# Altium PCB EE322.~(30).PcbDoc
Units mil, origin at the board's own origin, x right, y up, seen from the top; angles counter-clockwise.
Board outline 3640 x 2960 mil, 2 copper layers (Top Layer, Bottom Layer); 48 components, 23 nets, 113 pads, 0 vias.
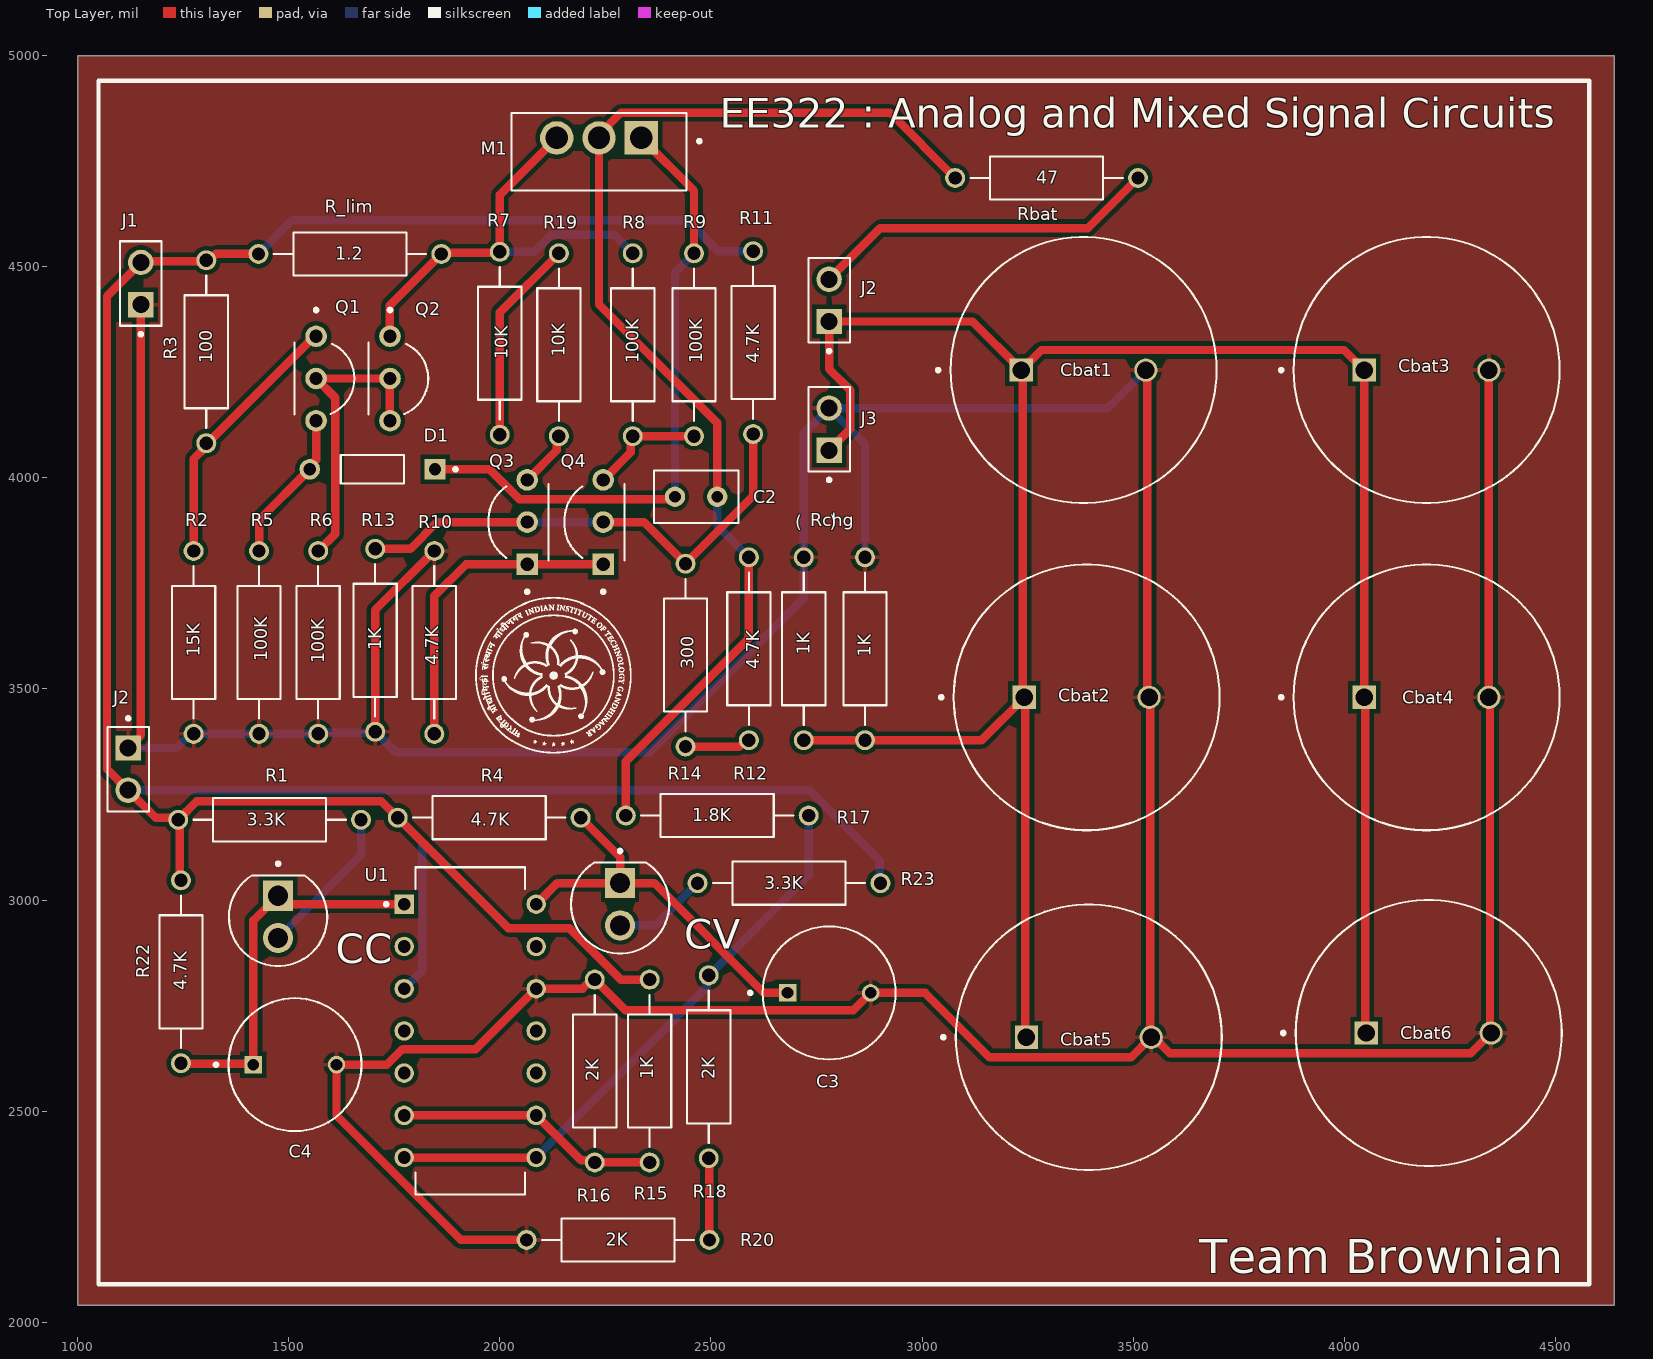
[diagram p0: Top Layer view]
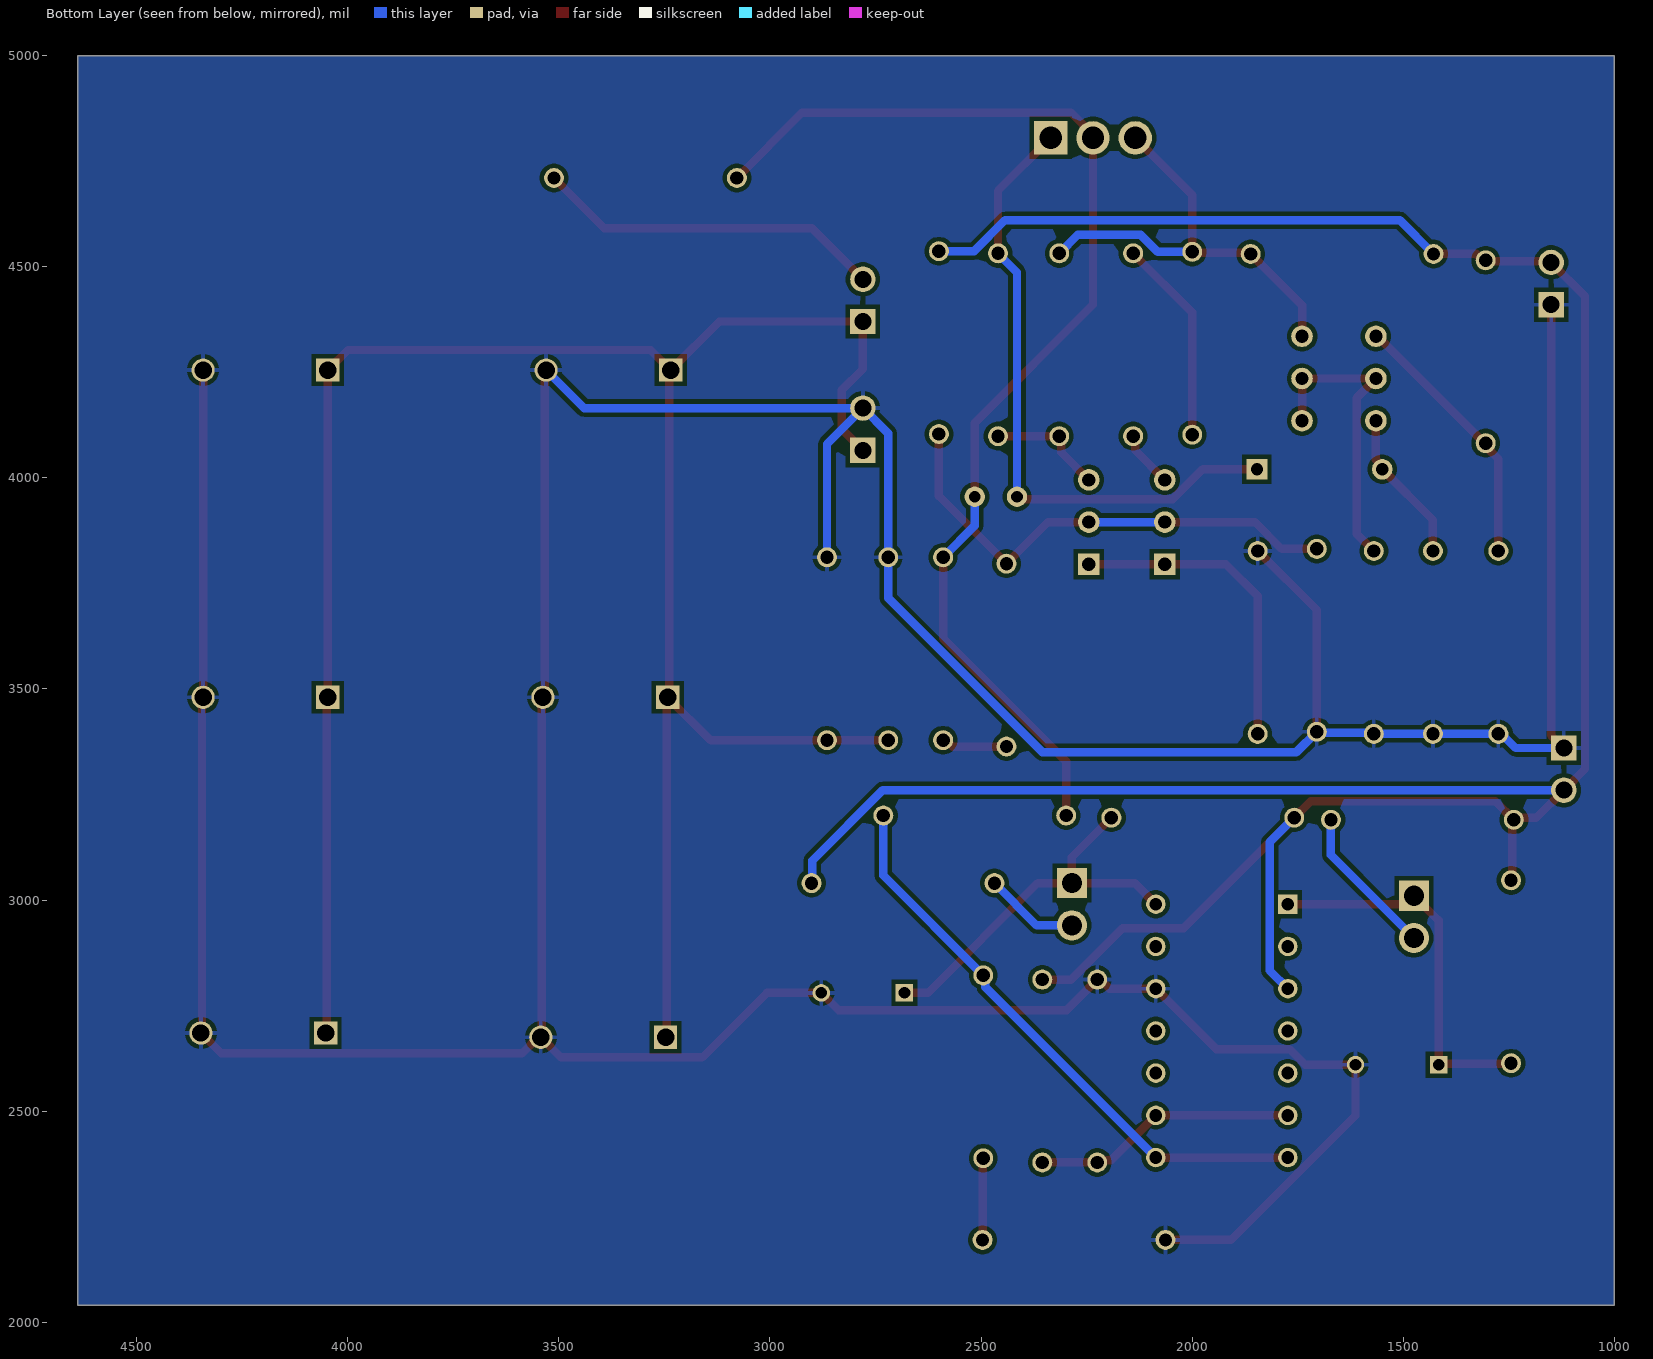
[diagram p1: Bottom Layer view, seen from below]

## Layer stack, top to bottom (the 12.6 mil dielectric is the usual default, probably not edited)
Top Solder: solder mask 0.4, Solder Resist, Dk 3.5
Top Layer: signal copper 1.4
Dielectric 1: dielectric 12.6, FR-4, Dk 4.8
Bottom Layer: signal copper 1.4
Bottom Solder: solder mask 0.4, Solder Resist, Dk 3.5

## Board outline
4640,5000 4640,2040 1000,2040 1000,5000

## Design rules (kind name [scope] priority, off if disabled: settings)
Clearance [All] p1: gap=10 ignorepadtopadclearanceinfootprint=FALSE
Height [All] p1: minheight=0 maxheight=1500 prefheight=500
PolygonConnect [All] p1: connectstyle=Relief reliefconductorwidth=10 reliefentries=4 polygonreliefangle="90 Angle" airgapwidth=10
RoutingVias [All] p1: holewidth=28 width=50 viastyle="Through Hole" minholewidth=28 minwidth=50 maxholewidth=28 maxwidth=50
SilkToSolderMaskClearance [IsPad] p1: minsilkscreentomaskgap=9 clearancetoexposedcopper=TRUE
SolderMaskExpansion [All] p1: expansion=0 istentingtop=FALSE
Width [All] p1: maxlimit=40 minlimit=20 preferedwidth=20
28 further rules are at their usual default settings.

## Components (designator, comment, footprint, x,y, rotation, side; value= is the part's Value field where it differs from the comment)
C2 "" CAPRR254W50L508T317H508 2465,3955 r0 top
C3 "ECEA1HKA330Q" CAPPRD500W45D800H700 2780,2780 r0 top
C4 "ECEA1HKA330Q" CAPPRD500W45D800H700 1515,2610 r0 top
Cbat1 "" CAPPRD750W80D1600H3150 3382.64,4255 r0 top
Cbat2 "" CAPPRD750W80D1600H3150 3390,3480 r0 top
Cbat3 "" CAPPRD750W80D1600H3150 4195,4255 r0 top
Cbat4 "" CAPPRD750W80D1600H3150 4195,3480 r0 top
Cbat5 "" CAPPRD750W80D1600H3150 3395,2675 r0 top
Cbat6 "" CAPPRD750W80D1600H3150 4200,2685 r0 top
CC "" LEDRD254W57D500H1070 1475,2960 r270 top
CV "" LEDRD254W57D500H1070 2285,2990 r270 top
D1 "1N4148" DIOAD753W49L380D172B 1698.37,4020 r180 top
J1 "" CONNFLY_DS1021-1X2SF11-B 1150,4460 r90 top
J2 "" CONNFLY_DS1021-1X2SF11-B 1120,3310 r270 top
J2 "" CONNFLY_DS1021-1X2SF11-B 2780,4420 r90 top
J3 "" CONNFLY_DS1021-1X2SF11-B 2780,4115 r90 top
M1 "" TO254P1052X465X1989-3 2335,4805 r180 top
Q1 "" TO92254P460H750-3#1 1565,4235 r270 top
Q2 "" TO92254P460H750-3#1 1740,4235 r270 top
Q3 "" TO92254P460H750-3#2 2065,3895 r90 top
Q4 "" TO92254P460H750-3#2 2245,3895 r90 top
R1 "" RESAD1100W55L680D260 1455,3190 r180 top
R2 "" RESAD1100W55L680D260 1275,3610 r90 top
R3 "" RESAD1100W55L680D260 1305,4298.46 r90 top
R4 "" RESAD1100W55L680D260 1975,3195 r180 top
R5 "" RESAD1100W55L680D260 1430,3610 r90 top
R6 "" RESAD1100W55L680D260 1570,3610 r90 top
R7 "" RESAD1100W55L680D260 2000,4318.46 r90 top
R8 "" RESAD1100W55L680D260 2315,4315 r90 top
R9 "" RESAD1100W55L680D260 2460,4315 r90 top
R10 "" RESAD1100W55L680D260 1845,3610 r270 top
R11 "" RESAD1100W55L680D260 2600,4320 r90 top
R12 "" RESAD1100W55L680D260 2590,3595 r90 top
R13 "" RESAD1100W55L680D260 1705,3615 r90 top
R14 "" RESAD1100W55L680D260 2440,3580 r270 top
R15 "MFR-25FBF52-10K" RESAD1100W55L680D260 2355,2595 r90 top
R16 "MFR-25FBF52-10K" RESAD1100W55L680D260 2225,2595 r270 top
R17 "MFR-25FBF52-10K" RESAD1100W55L680D260 2515,3200 r180 top
R18 "MFR-25FBF52-10K" RESAD1100W55L680D260 2495,2605 r90 top
R19 "" RESAD1100W55L680D260 2140,4315 r90 top
R20 "MFR-25FBF52-10K" RESAD1100W55L680D260 2280,2195 r0 top
R22 "" RESAD1100W55L680D260 1245,2830 r90 top
R23 "" RESAD1100W55L680D260 2685,3040 r0 top
R_lim "" RESAD1100W55L680D260 1645,4530 r0 top
Rbat "" RESAD1100W55L680D260 3295,4710 r180 top
Rchg "" RESAD1100W55L680D260 2720,3595 r270 top
Rchg1 "" RESAD1100W55L680D260 2865,3595 r270 top
U1 "LM339AN" DIP794W45P254L1969H508Q14 1930,2690 r0 top

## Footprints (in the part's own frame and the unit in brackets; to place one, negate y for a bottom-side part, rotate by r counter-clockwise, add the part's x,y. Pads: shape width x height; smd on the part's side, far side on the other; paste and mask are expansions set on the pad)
CAPPRD500W45D800H700 [mm]
  round 1.05 hole 0.7: N(2.5,0)
  rect 1.05x1.05 / inner round 1.05 / far side rect 1.05x1.05 hole 0.7: P(-2.5,0)
  silkscreen extent -4.85,-4 4,4, body extent -4,-4 4,4, height 7
CAPPRD750W80D1600H3150 [mm]
  round 1.4 hole 1.05: N(3.75,0)
  rect 1.4x1.4 hole 1.05: P(-3.75,0)
  silkscreen extent -8.85,-8 8,8, body extent -8,-8 8,8, height 31.5
CAPRR254W50L508T317H508 [mm]
  round 1.218 hole 0.71: 1(-1.27,0) 2(1.27,0)
  silkscreen extent -2.54,-1.59 2.54,1.59
CONNFLY_DS1021-1X2SF11-B [mm]
  rect 1.53x1.53 / inner round 1.53 / far side rect 1.53x1.53 hole 1.02 mask+0.102: 1(-1.27,0)
  round 1.53 hole 1.02 mask+0.102: 2(1.27,0)
  silkscreen extent -3.15,-1.25 2.54,1.25, body extent -2.54,-1.25 2.54,1.25, height 8.6
DIOAD753W49L380D172B [mm]
  round 1.238 hole 0.73 mask+0.102: A(3.768,0)
  rect 1.238x1.238 / inner round 1.238 / far side rect 1.238x1.238 hole 0.73 mask+0.102: K(-3.768,0)
  silkscreen extent -5.1,-0.86 1.9,0.86
DIP794W45P254L1969H508Q14 [mm]
  rect 1.17x1.17 / inner round 1.17 / far side rect 1.17x1.17 hole 0.77 mask+0.102: 1(-3.97,7.62)
  round 1.17 hole 0.77 mask+0.102: 2(-3.97,5.08) 3(-3.97,2.54) 4(-3.97,0) 5(-3.97,-2.54) 6(-3.97,-5.08) 7(-3.97,-7.62) 8(3.97,-7.62) 9(3.97,-5.08) 10(3.97,-2.54) 11(3.97,0) 12(3.97,2.54) 13(3.97,5.08) 14(3.97,7.62)
  silkscreen extent -5.15,-9.84 3.3,9.84, body extent -3.94,-9.65 3.94,9.65, height 5.08
LEDRD254W57D500H1070 [mm]
  round 1.815 hole 1.21: A(1.27,0)
  rect 1.815x1.815 / inner round 1.815 / far side rect 1.815x1.815 hole 1.21: C(-1.27,0)
  silkscreen extent -3.3,-2.96 2.96,2.96, body extent -2.6,-2.95 2.95,2.95, height 9.1
RESAD1100W55L680D260 [mm]
  round 1.2 hole 0.8: 1(-5.5,0) 2(5.5,0)
  silkscreen extent -4.58,-1.3 4.58,1.3, body extent -5.77,-1.2 5.77,1.2, height 2.4
TO254P1052X465X1989-3 [mm]
  rect 2.01x2.01 / inner round 2.01 / far side rect 2.01x2.01 hole 1.34: 1(0,0)
  round 2.01 hole 1.34: 2(2.54,0) 3(5.08,0)
  silkscreen extent -3.6,-1.5 7.8,3.16, body extent -5.12,-1.54 5.12,2.91, height 19.89
TO92254P460H750-3#1 [mm]
  round 1.298 hole 0.79 mask+0.102: 1(-2.54,0) 2(0,0) 3(2.54,0)
  silkscreen extent -4.22,-1.3 2.15,2.3, body extent -2.74,-1.27 2.74,2.33, height 8.09
TO92254P460H750-3#2 [mm]
  rect 1.298x1.298 / inner round 1.298 / far side rect 1.298x1.298 hole 0.79 mask+0.102: 1(-2.54,0)
  round 1.298 hole 0.79 mask+0.102: 2(0,0) 3(2.54,0)
  silkscreen extent -4.29,-1.27 2.3,2.33, body extent -2.74,-1.27 2.74,2.33, height 8.09

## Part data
C2: library part SR291C104KAR, "SR Series 5.08 x 5.08 mm 100 nF 100 V Â±10 % Tol. X7R Radial Lead/SkyCapÂ®", Package=None
C3 C4: "CAP ALUM 33UF 20% 50V RADIAL", Package="RADIAL-2 Panasonic"
Cbat1 Cbat2 Cbat3 Cbat4 Cbat5 Cbat6: library part ECA1HHG222, "Cap Aluminum 2200uF 50V 20% (16 X 31.5mm) Radial Aluminum Cylindrical Can 7.5mm 1470mA 2000 hr 105C Bulk", Package="RADIAL-2 Panasonic"
CC CV: library part L08R5000Q1, "LED, 5MM, ORANGE; LED / Lamp Size: 5mm / T-1 3/4; LED Colour: Orange; Typ Luminous Intensity: 4.3mcd; Viewing Angle: ...", Package=None
D1: "Diode Standard 75V 200mA Surface Mount SOD-523F", Package="AXIAL LEAD-2 ON Semiconductor"
J1 J2 J2 J3: library part DS1021-1X2SF11-B, "2 position 2.54mm single row vertical pin header", Package=None
M1: library part IRF9540, "P-Channel 100 V 19A (Tc) 3.7W (Ta), 150W (Tc) Surface Mount DÂ²PAK (TO-263)", Package="TO-220-3 Vishay"
Q1 Q2: library part 2N3906, "BJT, TO-92, 40V, 200mA, PNP, 0.625W, 150Â°C", Package="TO-92 Diotec"
Q3 Q4: library part 2N3904, "BJT, TO-92, 40V, 200mA, NPN, 0.625W, 150Â°C", Package="TO-92 Diotec"
R1 R2 R3 R4 R5 R6 R7 R8 R9 R10 R11 R12 R13 R14 R19 R22 R23 R_lim Rbat Rchg Rchg1: library part MFR-25FBF52-10K, "10.2 kOhms Â±1% 0.25W, 1/4W Through Hole Resistor Axial - Metal Film", Package="RADIAL-2 YAGEO"
R15 R16 R17 R18 R20: "10.2 kOhms Â±1% 0.25W, 1/4W Through Hole Resistor Axial - Metal Film", Package="RADIAL-2 YAGEO"
U1: "Precision quad differential comparator, commercial grade", Package="PDIP-14 Texas Instruments"

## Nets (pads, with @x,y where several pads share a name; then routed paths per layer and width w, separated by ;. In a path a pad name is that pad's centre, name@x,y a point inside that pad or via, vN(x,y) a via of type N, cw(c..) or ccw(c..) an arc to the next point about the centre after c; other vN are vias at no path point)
gnd: C3.N C4.N Cbat1.N Cbat2.N Cbat3.N Cbat4.N Cbat5.N Cbat6.N J1.1 J2.1@1120,3360 J3.2 R2.1 R5.1 R6.1 R10.1 R13.1 R16.1 R20.1 Rchg1.1 Rchg.1 U1.12 | length 11819.3
  Top Layer w20: J2.1@1120,3360 1150,3390 J1.1 ; R13.1 1705,3686.54 R10.1 ; R20.1 1907.85,2195 1613.43,2489.42 C4.N 1732.85,2610 1769.81,2646.97 1943.27,2646.97 U1.12 2196.09,2790 2217.63,2811.54 R16.1 2297.2,2739.33 2837.76,2739.33 C3.N 3007.42,2780 3159.98,2627.44 3495.08,2627.44 Cbat5.N ; Cbat1.N 3533.96,4251.32 3533.96,3483.68 Cbat2.N 3540.14,3477.5 3540.14,2677.5 Cbat5.N ; Cbat3.N Cbat4.N 4345.14,3477.5 4345.14,2687.5 Cbat6.N 4300.08,2637.44 3586.48,2637.44 3548.92,2675 Cbat5.N
  Bottom Layer w20: J2.1@1120,3360 1234.16,3360 1267.63,3393.46 R2.1 R5.1 R6.1 1572.5,3395.96 1702.5,3395.96 R13.1 1753.62,3349.84 2354.84,3349.84 2720,3715 Rchg.1 2720,4105 J3.2 ; Rchg1.1 2865,4080 J3.2 ; Cbat1.N 3440.28,4165 J3.2
NetC2_1: C2.1 D1.K M1.1 R9.2 | length 1520.2
  Top Layer w20: D1.K 1975.58,4020 2046.13,3949.45 2401.88,3949.45 2407.44,3955 C2.1 ; M1.1 2460,4680 R9.2
  Bottom Layer w20: C2.1 2415,4486.54 R9.2
NetC3_P: C3.P CV.C R4.1 U1.14 | length 917.4
  Top Layer w20: U1.14 2136.3,3040 CV.C ; R4.1 2285,3101.54 CV.C ; C3.P 2626.15,2780 2366.15,3040 CV.C
NetC4_P: C4.P CC.C R22.1 U1.1 | length 904.2
  Top Layer w20: R22.1 1246.73,2611.73 1414.84,2611.73 C4.P 1416.57,2951.57 CC.C 1495,2990 U1.1
NetCbat1_P: Cbat1.P Cbat2.P Cbat3.P Cbat4.P Cbat5.P Cbat6.P J2.1@2780,4370 J3.1 Rchg1.2 Rchg.2 | length 5422.5
  Top Layer w20: Rchg.2 Rchg1.2 3140.83,3378.46 Cbat2.P ; J3.1 2830.12,4115.12 2830.12,4207.44 2780,4257.56 2780,4370 3120,4370 Cbat1.P ; Cbat5.P 3244.86,2677.5 3244.86,3477.5 Cbat2.P ; Cbat6.P 4049.86,2687.5 4049.86,3477.5 Cbat4.P Cbat3.P 3999.8,4302.56 3282.56,4302.56 Cbat1.P ; Cbat1.P 3238.68,4251.32 3238.68,3483.68 Cbat2.P
NetCC_A: CC.A R1.1 | length 361.4
  Bottom Layer w20: CC.A 1671.54,3106.54 R1.1
NetCV_A: CV.A R23.1 | length 224.9
  Bottom Layer w20: CV.A 2368.46,2940 R23.1
NetD1_A: D1.A Q1.3 R5.2 | length 364.4
  Top Layer w20: R5.2 1430,3900 D1.A 1550,4027.78 1565,4042.78 Q1.3
NetJ2_2: J2.2@2780,4470 Rbat.1 | length 830.9
  Top Layer w20: J2.2@2780,4470 2901.24,4591.24 3392.78,4591.24 Rbat.1
NetM1_3: M1.3 Q2.1 R7.2 R8.2 R_lim.2 | length 1061.5
  Top Layer w20: Q2.1 1740,4408.46 R_lim.2 1864.04,4532.5 1997.5,4532.5 R7.2 2000,4670 M1.3
  Bottom Layer w20: R7.2 2081.77,4535 2121.93,4575.16 2271.38,4575.16 R8.2
NetQ1_1: Q1.1 R2.2 R3.1 | length 632.6
  Top Layer w20: R2.2 1275,4044.56 1305,4074.56 R3.1 1308.46,4081.93 1561.54,4335 Q1.1
NetQ1_2: Q1.2 Q2.2 Q2.3 R6.2 | length 719.1
  Top Layer w20: R6.2 1610.55,3867.09 1610.55,4189.45 Q1.2 Q2.2 Q2.3
NetQ3_1: Q3.1 Q4.1 R10.2 | length 757.6
  Top Layer w20: R10.2 1845,3720 1920,3795 Q3.1 Q4.1
NetQ3_2: Q3.2 Q4.2 R11.1 R13.2 R14.1 | length 1175.3
  Top Layer w20: R13.2 1788.31,3831.54 1851.77,3895 Q3.2 ; Q4.2 2341.54,3895 R14.1 2600,3956.54 R11.1
  Bottom Layer w20: Q3.2 Q4.2
NetQ3_3: Q3.3 R19.1 | length 134.5
  Top Layer w20: Q3.3 2134.79,4064.79 2134.79,4093.25 R19.1
NetQ4_3: Q4.3 R8.1 R9.1 | length 277.5
  Top Layer w20: Q4.3 2309.79,4059.79 2309.79,4093.25 R8.1 R9.1
NetR7_1: R7.1 R19.2 | length 487.6
  Top Layer w20: R7.1 2000,4391.54 R19.2
NetR12_1: R12.1 R14.2 | length 156.2
  Top Layer w20: R14.2 2567.63,3363.46 2582.63,3378.46 R12.1
NetR18_1: R18.1 R20.2 | length 194.1
  Top Layer w20: R18.1 2495.77,2387.7 2495.77,2195.77 R20.2
V1: R17.1 R18.2 U1.7 U1.8 | length 1389.9
  Top Layer w20: U1.7 U1.8
  Bottom Layer w20: U1.8 2489.79,2793.49 2489.79,2816.32 R18.2 2731.54,3058.07 R17.1
V2: R15.1 R16.2 U1.6 U1.9 | length 627.5
  Top Layer w20: U1.6 U1.9 2192.62,2383.68 2219.79,2383.68 R16.2 R15.1
VBat: C2.2 M1.2 R12.2 R17.2 Rbat.2 | length 2809.3
  Top Layer w20: R17.2 2298.46,3328.46 2590,3620 R12.2 ; C2.2 2515,4130 2235,4410 M1.2 2235,4812.42 2287.15,4864.57 2923.9,4864.57 Rbat.2
  Bottom Layer w20: C2.2 2515,3886.54 R12.2
vdd: J1.2 J2.2@1120,3260 R1.2 R3.2 R4.2 R11.2 R15.2 R22.2 R23.2 R_lim.1 U1.3 | length 6778.8
  Top Layer w20: R22.2 1241.73,3049.8 1241.73,3186.73 R1.2 ; R_lim.1 1327.37,4530 1312.37,4515 R3.2 1302.5,4512.5 1152.5,4512.5 J1.2 1069.88,4429.88 1069.88,3310.12 1120,3260 1184.84,3195.16 1233.31,3195.16 R1.2 ; R15.2 2286.69,2811.54 2165.19,2933.03 2020.43,2933.03 R4.2 1719.84,3233.62 1282.09,3233.62 R1.2
  Bottom Layer w20: J2.2@1120,3260 2733.23,3260 2899.6,3093.62 2899.6,3041.93 R23.2 ; R_lim.1 1508.46,4610 2443.23,4610 2516.69,4536.54 R11.2 ; R4.2 1816.73,3136.73 1816.73,2833.03 U1.3
pads on no net: U1.2 U1.4 U1.5 U1.10 U1.11 U1.13

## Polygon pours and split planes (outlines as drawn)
gnd on Top Layer "GND_L01_P000" (solid, pour order 0): 1000,5000 1000,2040 4640,2040 4640,5000
gnd on Bottom Layer "GND_L02_P001" (solid, pour order 1): 1000,5000 1000,2040 4640,2040 4640,5000

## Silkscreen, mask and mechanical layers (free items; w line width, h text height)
Top Overlay:
  drawing of 219 lines, arcs and shapes, not listed
  text "EE322 : Analog and Mixed Signal Circuits" at 2521,4829.33 h70
  text "47" at 3271,4696 h30
  text "1.2" at 1611,4516 h30
  text "10K" at 2154,4286 h30 r90
  text "10K" at 2019,4281 h30 r90
  text "100" at 1319,4271 h30 r90
  text "100K" at 2329,4271 h30 r90
  text "100K" at 2479,4271 h30 r90
  text "4.7K" at 2614,4271 h30 r90
  text "(     )" at 2700,3880 h30
  text "1K" at 1719,3591 h30 r90
  text "1K" at 2734,3581 h30 r90
  text "15K" at 1289,3576 h30 r90
  text "1K" at 2879,3576 h30 r90
  text "100K" at 1449,3566 h30 r90
  text "100K" at 1584,3561 h30 r90
  text "4.7K" at 1854,3556 h30 r90
  text "300" at 2459,3546 h30 r90
  text "4.7K" at 2614,3546 h30 r90
  text "1.8K" at 2456,3186 h30
  text "3.3K" at 1401,3176 h30
  text "4.7K" at 1931,3176 h30
  text "3.3K" at 2626,3026 h30
  text "4.7K" at 1259,2786 h30 r90
  text "1K" at 2364,2576 h30 r90
  text "2K" at 2509,2576 h30 r90
  text "2K" at 2234,2571 h30 r90
  text "2K" at 2251,2181 h30
  text "Team Brownian" at 3656,2116 h80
